// Mitsubishi GX Works2 project: 38.机械手臂工作（跳转指令）   PLC: FX3U/FX3UC

PROGRAM MAIN
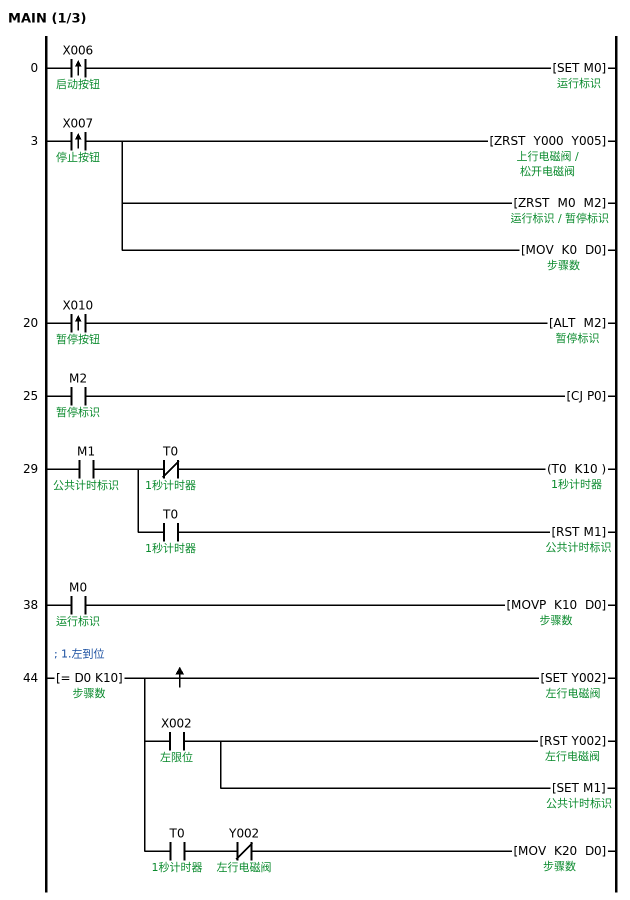
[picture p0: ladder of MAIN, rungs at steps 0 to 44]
0     LDP     X006  ; 启动按钮
      SET     M0  ; 运行标识
3     LDP     X007  ; 停止按钮
      ZRST    Y000 Y005  ; 上行电磁阀 / 松开电磁阀
      ZRST    M0 M2  ; 暂停标识
      MOV     K0 D0  ; 步骤数
20    LDP     X010  ; 暂停按钮
      ALT     M2
25    LD      M2  ; 暂停标识
      CJ      P0
29    LD      M1  ; 公共计时标识
      MPS
      ANI     T0  ; 1秒计时器
      OUT     T0 K10  ; 1秒计时器
      MPP
      AND     T0  ; 1秒计时器
      RST     M1  ; 公共计时标识
38    LD      M0  ; 运行标识
      MOVP    K10 D0
; 1.左到位
44    LD=     D0 K10  ; 步骤数
      MPS
      MEP
      SET     Y002  ; 左行电磁阀
      MRD
      AND     X002  ; 左限位
      RST     Y002  ; 左行电磁阀
      SET     M1  ; 公共计时标识
      MPP
      AND     T0  ; 1秒计时器
      ANI     Y002  ; 左行电磁阀
      MOV     K20 D0
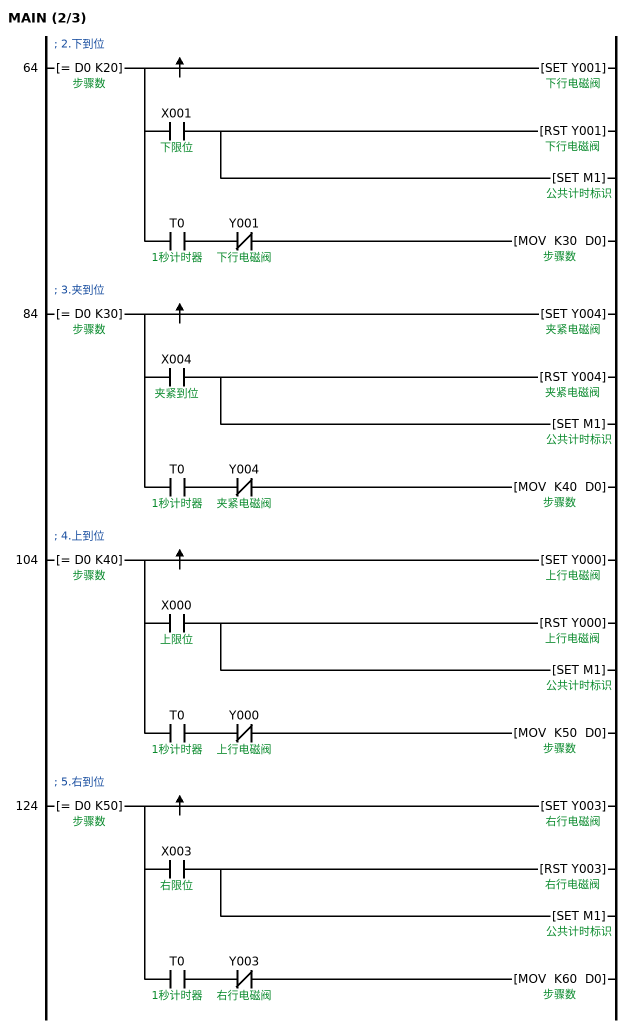
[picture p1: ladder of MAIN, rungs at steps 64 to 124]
; 2.下到位
64    LD=     D0 K20  ; 步骤数
      MPS
      MEP
      SET     Y001  ; 下行电磁阀
      MRD
      AND     X001  ; 下限位
      RST     Y001  ; 下行电磁阀
      SET     M1  ; 公共计时标识
      MPP
      AND     T0  ; 1秒计时器
      ANI     Y001  ; 下行电磁阀
      MOV     K30 D0
; 3.夹到位
84    LD=     D0 K30  ; 步骤数
      MPS
      MEP
      SET     Y004  ; 夹紧电磁阀
      MRD
      AND     X004  ; 夹紧到位
      RST     Y004  ; 夹紧电磁阀
      SET     M1  ; 公共计时标识
      MPP
      AND     T0  ; 1秒计时器
      ANI     Y004  ; 夹紧电磁阀
      MOV     K40 D0
; 4.上到位
104   LD=     D0 K40  ; 步骤数
      MPS
      MEP
      SET     Y000  ; 上行电磁阀
      MRD
      AND     X000  ; 上限位
      RST     Y000  ; 上行电磁阀
      SET     M1  ; 公共计时标识
      MPP
      AND     T0  ; 1秒计时器
      ANI     Y000  ; 上行电磁阀
      MOV     K50 D0
; 5.右到位
124   LD=     D0 K50  ; 步骤数
      MPS
      MEP
      SET     Y003  ; 右行电磁阀
      MRD
      AND     X003  ; 右限位
      RST     Y003  ; 右行电磁阀
      SET     M1  ; 公共计时标识
      MPP
      AND     T0  ; 1秒计时器
      ANI     Y003  ; 右行电磁阀
      MOV     K60 D0
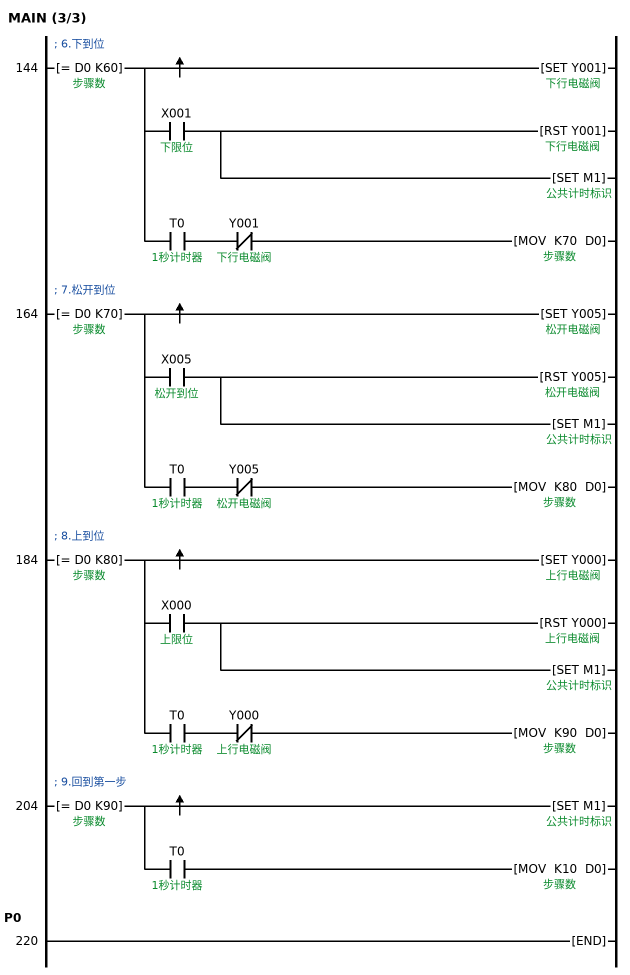
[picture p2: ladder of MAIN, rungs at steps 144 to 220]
; 6.下到位
144   LD=     D0 K60  ; 步骤数
      MPS
      MEP
      SET     Y001  ; 下行电磁阀
      MRD
      AND     X001  ; 下限位
      RST     Y001  ; 下行电磁阀
      SET     M1  ; 公共计时标识
      MPP
      AND     T0  ; 1秒计时器
      ANI     Y001  ; 下行电磁阀
      MOV     K70 D0
; 7.松开到位
164   LD=     D0 K70  ; 步骤数
      MPS
      MEP
      SET     Y005  ; 松开电磁阀
      MRD
      AND     X005  ; 松开到位
      RST     Y005  ; 松开电磁阀
      SET     M1  ; 公共计时标识
      MPP
      AND     T0  ; 1秒计时器
      ANI     Y005  ; 松开电磁阀
      MOV     K80 D0
; 8.上到位
184   LD=     D0 K80  ; 步骤数
      MPS
      MEP
      SET     Y000  ; 上行电磁阀
      MRD
      AND     X000  ; 上限位
      RST     Y000  ; 上行电磁阀
      SET     M1  ; 公共计时标识
      MPP
      AND     T0  ; 1秒计时器
      ANI     Y000  ; 上行电磁阀
      MOV     K90 D0
; 9.回到第一步
204   LD=     D0 K90  ; 步骤数
      MPS
      MEP
      SET     M1  ; 公共计时标识
      MPP
      AND     T0  ; 1秒计时器
      MOV     K10 D0
      P0
220   END
END_PROGRAM

// device comments not shown above
D1  ; 暂停前步骤数
